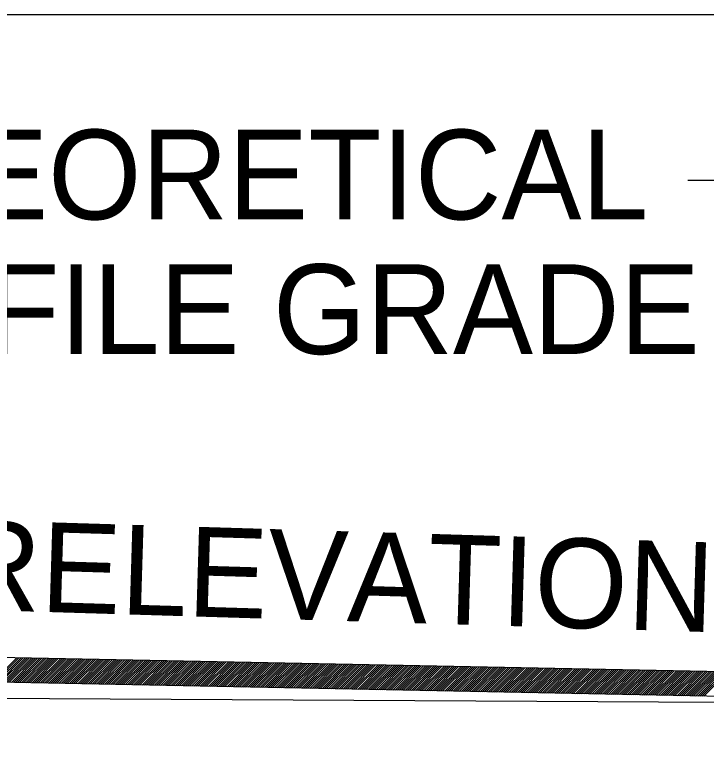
# Model space of a CAD drawing. Extents: x 2478 to 3210, y 439 to 841.
# Drawn here: x 3017.74 to 3026.98, y 785.11 to 795.13 of the extents above; entities that cross this region are included whole.
import ezdxf

# ---------------------------------------------------------------- set-up
doc = ezdxf.new("R2010")
doc.units = 0
for name, color, linetype in [('19', 7, 'Continuous'), ('R_Annotation', 7, 'Continuous'), ('R_Dimension', 7, 'Continuous'), ('R_Exist Surface', 7, 'Continuous')]:
    doc.layers.add(name, color=color, linetype=linetype)

msp = doc.modelspace()

# ---------------------------------------------------------------- linework, layer by layer
at = {"layer": '19'}
for p, q in [((3017.765, 786.533), (3017.441, 786.209)), ((3017.792, 786.532), (3017.469, 786.208)), ((3017.82, 786.532), (3017.497, 786.208)), ((3017.848, 786.531), (3017.524, 786.207)), ((3017.876, 786.53), (3017.552, 786.207)), ((3017.903, 786.53), (3017.58, 786.206)), ((3017.931, 786.529), (3017.608, 786.206)), ((3017.959, 786.529), (3017.635, 786.205)), ((3017.987, 786.528), (3017.663, 786.205)), ((3018.014, 786.528), (3017.691, 786.204)), ((3018.042, 786.527), (3017.718, 786.203)), ((3018.07, 786.527), (3017.746, 786.203)), ((3018.097, 786.526), (3017.774, 786.202)), ((3018.125, 786.525), (3017.802, 786.202)), ((3018.153, 786.525), (3017.829, 786.201)), ((3018.181, 786.524), (3017.857, 786.201)), ((3018.208, 786.524), (3017.885, 786.2)), ((3018.236, 786.523), (3017.913, 786.2)), ((3018.264, 786.523), (3017.94, 786.199)), ((3018.292, 786.522), (3017.968, 786.198)), ((3018.319, 786.522), (3017.996, 786.198)), ((3018.347, 786.521), (3018.023, 786.197)), ((3018.375, 786.52), (3018.051, 786.197)), ((3018.403, 786.52), (3018.079, 786.196)), ((3018.43, 786.519), (3018.107, 786.196)), ((3018.458, 786.519), (3018.134, 786.195)), ((3018.486, 786.518), (3018.162, 786.195)), ((3018.513, 786.518), (3018.19, 786.194)), ((3018.541, 786.517), (3018.218, 786.194)), ((3018.569, 786.517), (3018.245, 786.193)), ((3018.597, 786.516), (3018.273, 786.192)), ((3018.624, 786.515), (3018.301, 786.192)), ((3018.652, 786.515), (3018.328, 786.191)), ((3018.68, 786.514), (3018.356, 786.191)), ((3018.708, 786.514), (3018.384, 786.19)), ((3018.735, 786.513), (3018.412, 786.19)), ((3018.763, 786.513), (3018.439, 786.189)), ((3018.791, 786.512), (3018.467, 786.189)), ((3018.818, 786.512), (3018.495, 786.188)), ((3018.846, 786.511), (3018.523, 786.187)), ((3018.874, 786.51), (3018.55, 786.187)), ((3018.902, 786.51), (3018.578, 786.186)), ((3018.929, 786.509), (3018.606, 786.186)), ((3018.957, 786.509), (3018.634, 786.185)), ((3018.985, 786.508), (3018.661, 786.185)), ((3019.013, 786.508), (3018.689, 786.184)), ((3019.04, 786.507), (3018.717, 786.184)), ((3019.068, 786.507), (3018.744, 786.183)), ((3019.096, 786.506), (3018.772, 786.182)), ((3019.123, 786.505), (3018.8, 786.182)), ((3019.151, 786.505), (3018.828, 786.181)), ((3019.179, 786.504), (3018.855, 786.181)), ((3019.207, 786.504), (3018.883, 786.18)), ((3019.234, 786.503), (3018.911, 786.18)), ((3019.262, 786.503), (3018.939, 786.179)), ((3019.29, 786.502), (3018.966, 786.179)), ((3019.318, 786.502), (3018.994, 786.178)), ((3019.345, 786.501), (3019.022, 786.177)), ((3019.373, 786.5), (3019.049, 786.177)), ((3019.401, 786.5), (3019.077, 786.176)), ((3019.429, 786.499), (3019.105, 786.176)), ((3019.456, 786.499), (3019.133, 786.175)), ((3019.484, 786.498), (3019.16, 786.175)), ((3019.512, 786.498), (3019.188, 786.174)), ((3019.539, 786.497), (3019.216, 786.174)), ((3019.567, 786.497), (3019.244, 786.173)), ((3019.595, 786.496), (3019.271, 786.172)), ((3019.623, 786.495), (3019.299, 786.172)), ((3019.65, 786.495), (3019.327, 786.171)), ((3019.678, 786.494), (3019.354, 786.171)), ((3019.706, 786.494), (3019.382, 786.17)), ((3019.734, 786.493), (3019.41, 786.17)), ((3019.761, 786.493), (3019.438, 786.169)), ((3019.789, 786.492), (3019.465, 786.169)), ((3019.817, 786.492), (3019.493, 786.168)), ((3019.844, 786.491), (3019.521, 786.167)), ((3019.872, 786.49), (3019.549, 786.167)), ((3019.9, 786.49), (3019.576, 786.166)), ((3019.928, 786.489), (3019.604, 786.166)), ((3019.955, 786.489), (3019.632, 786.165)), ((3019.983, 786.488), (3019.66, 786.165)), ((3020.011, 786.488), (3019.687, 786.164)), ((3020.039, 786.487), (3019.715, 786.164)), ((3020.066, 786.487), (3019.743, 786.163)), ((3020.094, 786.486), (3019.77, 786.162)), ((3020.122, 786.485), (3019.798, 786.162)), ((3020.149, 786.485), (3019.826, 786.161)), ((3020.177, 786.484), (3019.854, 786.161)), ((3020.205, 786.484), (3019.881, 786.16)), ((3020.233, 786.483), (3019.909, 786.16)), ((3020.26, 786.483), (3019.937, 786.159)), ((3020.288, 786.482), (3019.965, 786.159)), ((3020.316, 786.482), (3019.992, 786.158)), ((3020.344, 786.481), (3020.02, 786.157)), ((3020.371, 786.48), (3020.048, 786.157)), ((3020.399, 786.48), (3020.075, 786.156)), ((3020.427, 786.479), (3020.103, 786.156)), ((3020.455, 786.479), (3020.131, 786.155)), ((3020.482, 786.478), (3020.159, 786.155)), ((3020.51, 786.478), (3020.186, 786.154)), ((3020.538, 786.477), (3020.214, 786.154)), ((3020.565, 786.477), (3020.242, 786.153)), ((3020.593, 786.476), (3020.27, 786.152)), ((3020.621, 786.476), (3020.297, 786.152)), ((3020.649, 786.475), (3020.325, 786.151)), ((3020.676, 786.474), (3020.353, 786.151)), ((3020.704, 786.474), (3020.38, 786.15)), ((3020.732, 786.473), (3020.408, 786.15)), ((3020.76, 786.473), (3020.436, 786.149)), ((3020.787, 786.472), (3020.464, 786.149)), ((3020.815, 786.472), (3020.491, 786.148)), ((3020.843, 786.471), (3020.519, 786.147)), ((3020.87, 786.471), (3020.547, 786.147)), ((3020.898, 786.47), (3020.575, 786.146)), ((3020.926, 786.469), (3020.602, 786.146)), ((3020.954, 786.469), (3020.63, 786.145)), ((3020.981, 786.468), (3020.658, 786.145)), ((3021.009, 786.468), (3020.686, 786.144)), ((3021.037, 786.467), (3020.713, 786.144)), ((3021.065, 786.467), (3020.741, 786.143)), ((3021.092, 786.466), (3020.769, 786.142)), ((3021.12, 786.466), (3020.796, 786.142)), ((3021.148, 786.465), (3020.824, 786.141)), ((3021.175, 786.464), (3020.852, 786.141)), ((3021.203, 786.464), (3020.88, 786.14)), ((3021.231, 786.463), (3020.907, 786.14)), ((3021.259, 786.463), (3020.935, 786.139)), ((3021.286, 786.462), (3020.963, 786.139)), ((3021.314, 786.462), (3020.991, 786.138)), ((3021.342, 786.461), (3021.018, 786.137)), ((3021.37, 786.461), (3021.046, 786.137)), ((3021.397, 786.46), (3021.074, 786.136)), ((3021.425, 786.459), (3021.101, 786.136)), ((3021.453, 786.459), (3021.129, 786.135)), ((3021.481, 786.458), (3021.157, 786.135)), ((3021.508, 786.458), (3021.185, 786.134)), ((3021.536, 786.457), (3021.212, 786.134)), ((3021.564, 786.457), (3021.24, 786.133)), ((3021.591, 786.456), (3021.268, 786.133)), ((3021.619, 786.456), (3021.296, 786.132)), ((3021.647, 786.455), (3021.323, 786.131)), ((3021.675, 786.454), (3021.351, 786.131)), ((3021.702, 786.454), (3021.379, 786.13)), ((3021.73, 786.453), (3021.406, 786.13)), ((3021.758, 786.453), (3021.434, 786.129)), ((3021.786, 786.452), (3021.462, 786.129)), ((3021.813, 786.452), (3021.49, 786.128)), ((3021.841, 786.451), (3021.517, 786.128)), ((3021.869, 786.451), (3021.545, 786.127)), ((3021.896, 786.45), (3021.573, 786.126)), ((3021.924, 786.449), (3021.601, 786.126)), ((3021.952, 786.449), (3021.628, 786.125)), ((3021.98, 786.448), (3021.656, 786.125)), ((3022.007, 786.448), (3021.684, 786.124)), ((3022.035, 786.447), (3021.712, 786.124)), ((3022.063, 786.447), (3021.739, 786.123)), ((3022.091, 786.446), (3021.767, 786.123)), ((3022.118, 786.446), (3021.795, 786.122)), ((3022.146, 786.445), (3021.822, 786.121)), ((3022.174, 786.444), (3021.85, 786.121)), ((3022.201, 786.444), (3021.878, 786.12)), ((3022.229, 786.443), (3021.906, 786.12)), ((3022.257, 786.443), (3021.933, 786.119)), ((3022.285, 786.442), (3021.961, 786.119)), ((3022.312, 786.442), (3021.989, 786.118)), ((3022.34, 786.441), (3022.017, 786.118)), ((3022.368, 786.441), (3022.044, 786.117)), ((3022.396, 786.44), (3022.072, 786.116)), ((3022.423, 786.439), (3022.1, 786.116)), ((3022.451, 786.439), (3022.127, 786.115)), ((3022.479, 786.438), (3022.155, 786.115)), ((3022.507, 786.438), (3022.183, 786.114)), ((3022.534, 786.437), (3022.211, 786.114)), ((3022.562, 786.437), (3022.238, 786.113)), ((3022.59, 786.436), (3022.266, 786.113)), ((3022.617, 786.436), (3022.294, 786.112)), ((3022.645, 786.435), (3022.322, 786.111)), ((3022.673, 786.434), (3022.349, 786.111)), ((3022.701, 786.434), (3022.377, 786.11)), ((3022.728, 786.433), (3022.405, 786.11)), ((3022.756, 786.433), (3022.432, 786.109)), ((3022.784, 786.432), (3022.46, 786.109)), ((3022.812, 786.432), (3022.488, 786.108)), ((3022.839, 786.431), (3022.516, 786.108)), ((3022.867, 786.431), (3022.543, 786.107)), ((3022.895, 786.43), (3022.571, 786.106)), ((3022.922, 786.429), (3022.599, 786.106)), ((3022.95, 786.429), (3022.627, 786.105)), ((3022.978, 786.428), (3022.654, 786.105)), ((3023.006, 786.428), (3022.682, 786.104)), ((3023.033, 786.427), (3022.71, 786.104)), ((3023.061, 786.427), (3022.738, 786.103)), ((3023.089, 786.426), (3022.765, 786.103)), ((3023.117, 786.426), (3022.793, 786.102)), ((3023.144, 786.425), (3022.821, 786.101)), ((3023.172, 786.424), (3022.848, 786.101)), ((3023.2, 786.424), (3022.876, 786.1)), ((3023.227, 786.423), (3022.904, 786.1)), ((3023.255, 786.423), (3022.932, 786.099)), ((3023.283, 786.422), (3022.959, 786.099)), ((3023.311, 786.422), (3022.987, 786.098)), ((3023.338, 786.421), (3023.015, 786.098)), ((3023.366, 786.421), (3023.043, 786.097)), ((3023.394, 786.42), (3023.07, 786.096)), ((3023.422, 786.419), (3023.098, 786.096)), ((3023.449, 786.419), (3023.126, 786.095)), ((3023.477, 786.418), (3023.153, 786.095)), ((3023.505, 786.418), (3023.181, 786.094)), ((3023.533, 786.417), (3023.209, 786.094)), ((3023.56, 786.417), (3023.237, 786.093)), ((3023.588, 786.416), (3023.264, 786.093)), ((3023.616, 786.416), (3023.292, 786.092)), ((3023.643, 786.415), (3023.32, 786.091)), ((3023.671, 786.415), (3023.348, 786.091)), ((3023.699, 786.414), (3023.375, 786.09)), ((3023.727, 786.413), (3023.403, 786.09)), ((3023.754, 786.413), (3023.431, 786.089)), ((3023.782, 786.412), (3023.458, 786.089)), ((3023.81, 786.412), (3023.486, 786.088)), ((3023.838, 786.411), (3023.514, 786.088)), ((3023.865, 786.411), (3023.542, 786.087)), ((3023.893, 786.41), (3023.569, 786.086)), ((3023.921, 786.41), (3023.597, 786.086)), ((3023.948, 786.409), (3023.625, 786.085)), ((3023.976, 786.408), (3023.653, 786.085)), ((3024.004, 786.408), (3023.68, 786.084)), ((3024.032, 786.407), (3023.708, 786.084)), ((3024.059, 786.407), (3023.736, 786.083)), ((3024.087, 786.406), (3023.764, 786.083)), ((3024.115, 786.406), (3023.791, 786.082)), ((3024.143, 786.405), (3023.819, 786.081)), ((3024.17, 786.405), (3023.847, 786.081)), ((3024.198, 786.404), (3023.874, 786.08)), ((3024.226, 786.403), (3023.902, 786.08)), ((3024.253, 786.403), (3023.93, 786.079)), ((3024.281, 786.402), (3023.958, 786.079)), ((3024.309, 786.402), (3023.985, 786.078)), ((3024.337, 786.401), (3024.013, 786.078)), ((3024.364, 786.401), (3024.041, 786.077)), ((3024.392, 786.4), (3024.069, 786.076)), ((3024.42, 786.4), (3024.096, 786.076)), ((3024.448, 786.399), (3024.124, 786.075)), ((3024.475, 786.398), (3024.152, 786.075)), ((3024.503, 786.398), (3024.179, 786.074)), ((3024.531, 786.397), (3024.207, 786.074)), ((3024.559, 786.397), (3024.235, 786.073)), ((3024.586, 786.396), (3024.263, 786.073)), ((3024.614, 786.396), (3024.29, 786.072)), ((3024.642, 786.395), (3024.318, 786.071)), ((3024.669, 786.395), (3024.346, 786.071)), ((3024.697, 786.394), (3024.374, 786.07)), ((3024.725, 786.393), (3024.401, 786.07)), ((3024.753, 786.393), (3024.429, 786.069)), ((3024.78, 786.392), (3024.457, 786.069)), ((3024.808, 786.392), (3024.484, 786.068)), ((3024.836, 786.391), (3024.512, 786.068)), ((3024.864, 786.391), (3024.54, 786.067)), ((3024.891, 786.39), (3024.568, 786.067)), ((3024.919, 786.39), (3024.595, 786.066)), ((3024.947, 786.389), (3024.623, 786.065)), ((3024.974, 786.388), (3024.651, 786.065)), ((3025.002, 786.388), (3024.679, 786.064)), ((3025.03, 786.387), (3024.706, 786.064)), ((3025.058, 786.387), (3024.734, 786.063)), ((3025.085, 786.386), (3024.762, 786.063)), ((3025.113, 786.386), (3024.79, 786.062)), ((3025.141, 786.385), (3024.817, 786.062)), ((3025.169, 786.385), (3024.845, 786.061)), ((3025.196, 786.384), (3024.873, 786.06)), ((3025.224, 786.383), (3024.9, 786.06)), ((3025.252, 786.383), (3024.928, 786.059)), ((3025.279, 786.382), (3024.956, 786.059)), ((3025.307, 786.382), (3024.984, 786.058)), ((3025.335, 786.381), (3025.011, 786.058)), ((3025.363, 786.381), (3025.039, 786.057)), ((3025.39, 786.38), (3025.067, 786.057)), ((3025.418, 786.38), (3025.095, 786.056)), ((3025.446, 786.379), (3025.122, 786.055)), ((3025.474, 786.378), (3025.15, 786.055)), ((3025.501, 786.378), (3025.178, 786.054)), ((3025.529, 786.377), (3025.205, 786.054)), ((3025.557, 786.377), (3025.233, 786.053)), ((3025.585, 786.376), (3025.261, 786.053)), ((3025.612, 786.376), (3025.289, 786.052)), ((3025.64, 786.375), (3025.316, 786.052)), ((3025.668, 786.375), (3025.344, 786.051)), ((3025.695, 786.374), (3025.372, 786.05)), ((3025.723, 786.373), (3025.4, 786.05)), ((3025.751, 786.373), (3025.427, 786.049)), ((3025.779, 786.372), (3025.455, 786.049)), ((3025.806, 786.372), (3025.483, 786.048)), ((3025.834, 786.371), (3025.51, 786.048)), ((3025.862, 786.371), (3025.538, 786.047)), ((3025.89, 786.37), (3025.566, 786.047)), ((3025.917, 786.37), (3025.594, 786.046)), ((3025.945, 786.369), (3025.621, 786.045)), ((3025.973, 786.368), (3025.649, 786.045)), ((3026, 786.368), (3025.677, 786.044)), ((3026.028, 786.367), (3025.705, 786.044)), ((3026.056, 786.367), (3025.732, 786.043)), ((3026.084, 786.366), (3025.76, 786.043)), ((3026.111, 786.366), (3025.788, 786.042)), ((3026.139, 786.365), (3025.816, 786.042)), ((3026.167, 786.365), (3025.843, 786.041)), ((3026.195, 786.364), (3025.871, 786.04)), ((3026.222, 786.363), (3025.899, 786.04)), ((3026.25, 786.363), (3025.926, 786.039)), ((3026.278, 786.362), (3025.954, 786.039)), ((3026.305, 786.362), (3025.982, 786.038)), ((3026.333, 786.361), (3026.01, 786.038)), ((3026.361, 786.361), (3026.037, 786.037)), ((3026.389, 786.36), (3026.065, 786.037)), ((3026.416, 786.36), (3026.093, 786.036)), ((3026.444, 786.359), (3026.121, 786.035)), ((3026.472, 786.358), (3026.148, 786.035)), ((3026.5, 786.358), (3026.176, 786.034)), ((3026.527, 786.357), (3026.204, 786.034)), ((3026.555, 786.357), (3026.231, 786.033)), ((3026.583, 786.356), (3026.259, 786.033)), ((3026.61, 786.356), (3026.287, 786.032)), ((3026.638, 786.355), (3026.315, 786.032)), ((3026.666, 786.355), (3026.342, 786.031)), ((3026.694, 786.354), (3026.37, 786.03)), ((3026.721, 786.353), (3026.398, 786.03)), ((3026.749, 786.353), (3026.426, 786.029)), ((3026.777, 786.352), (3026.453, 786.029)), ((3026.805, 786.352), (3026.481, 786.028)), ((3026.832, 786.351), (3026.509, 786.028)), ((3026.86, 786.351), (3026.536, 786.027)), ((3026.888, 786.35), (3026.564, 786.027)), ((3026.916, 786.35), (3026.592, 786.026)), ((3026.943, 786.349), (3026.62, 786.025)), ((3026.971, 786.349), (3026.647, 786.025)), ((3026.999, 786.348), (3026.675, 786.024)), ((3027.026, 786.347), (3026.703, 786.024)), ((3027.054, 786.347), (3026.731, 786.023)), ((3027.082, 786.346), (3026.758, 786.023)), ((3027.11, 786.346), (3026.786, 786.022)), ((3027.137, 786.345), (3026.814, 786.022)), ((3027.165, 786.345), (3026.841, 786.021)), ((3027.193, 786.344), (3026.869, 786.02)), ((3027.221, 786.344), (3026.897, 786.02)), ((3027.248, 786.343), (3026.925, 786.019)), ((3027.276, 786.342), (3026.952, 786.019))]:
    msp.add_line(p, q, dxfattribs=at)
at = {"layer": 'R_Annotation'}
for p, q in [((3031.233, 786.263), (3009.233, 786.703)), ((3031.227, 785.933), (3009.227, 786.373))]:
    msp.add_line(p, q, dxfattribs=at)
at = {"layer": 'R_Dimension'}
msp.add_line((3070.657, 795.13), (2989.723, 795.13), dxfattribs=at)
msp.add_lwpolyline([(3031.233, 786.263), (3028.606, 792.916), (3026.738, 792.916)], dxfattribs=at)
at = {"layer": 'R_Exist Surface'}
msp.add_lwpolyline([(2974.394, 779.542), (2980.464, 779.356), (2991.6, 780.578), (3008.322, 785.91), (3009.233, 786.036), (3031.233, 785.919), (3053.233, 785.156), (3055.82, 784.789), (3076.957, 782.83), (3083.428, 781.714), (3088.64, 782.82)], dxfattribs=at)

# ---------------------------------------------------------------- texts
at = {"layer": 'R_Annotation'}
for s, p in [('THEORETICAL ', (3014.973, 792.396)), ('PROFILE GRADE', (3013.877, 790.596))]:
    msp.add_text(s, height=1.2, dxfattribs=at).set_placement(p)
msp.add_text('SUPERELEVATION', height=1.2, rotation=358.2609, dxfattribs=at).set_placement((3012.545, 787.316))

doc.saveas('drawing.dxf')
